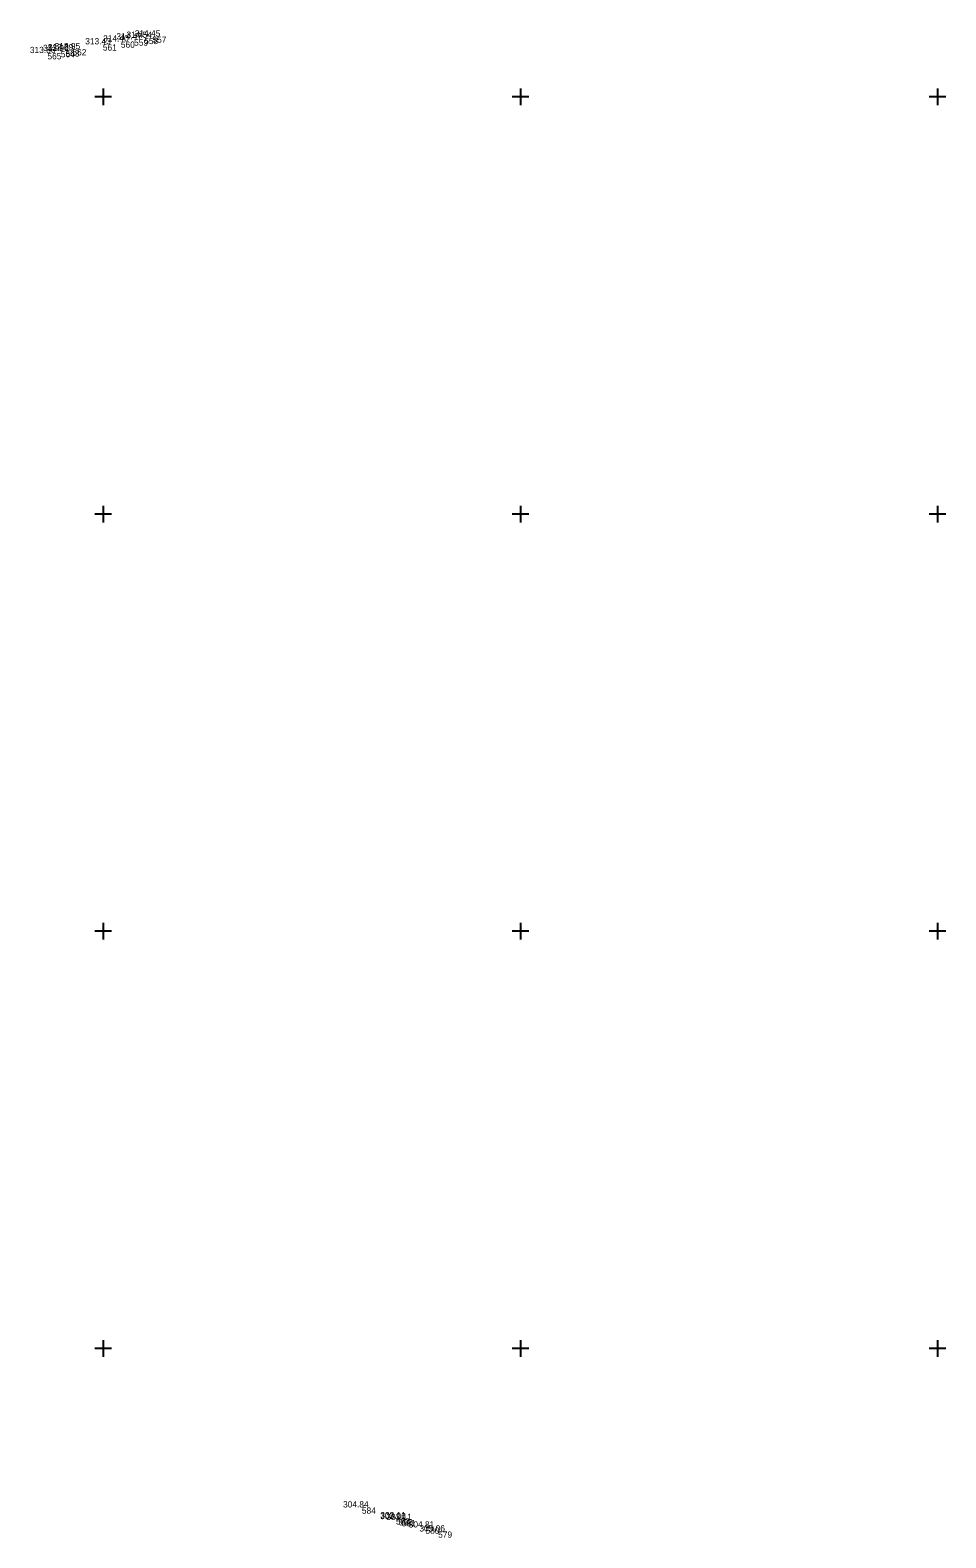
# Model space of a CAD drawing. Extents: x -718951 to -718443, y -1070201 to -1068444.
# Drawn here: x -718858.8 to -718749, y -1069972.7 to -1069792 of the extents above; entities that cross this region are included whole.
import ezdxf

# ---------------------------------------------------------------- set-up
doc = ezdxf.new("R2010")
doc.units = 0
for name, color, linetype in [('GEO_Body polohopis', 7, 'Continuous'), ('GEO_Hektarová síť', 7, 'Continuous'), ('GEO_Výšky bodů polohopis', 7, 'Continuous'), ('GEO_Čísla bodů polohopis', 7, 'Continuous')]:
    doc.layers.add(name, color=color, linetype=linetype)

msp = doc.modelspace()

# ---------------------------------------------------------------- linework, layer by layer
at = {"layer": 'GEO_Body polohopis'}
for p, q in [((-718855.09, -1069794.5), (-718855.09, -1069794.5)), ((-718854.52, -1069794.41), (-718854.52, -1069794.41)), ((-718853.7, -1069794.28), (-718853.7, -1069794.28)), ((-718850.05, -1069793.7), (-718850.05, -1069793.7)), ((-718847.89, -1069793.36), (-718847.89, -1069793.36)), ((-718846.3, -1069793.11), (-718846.3, -1069793.11)), ((-718845.09, -1069792.92), (-718845.09, -1069792.92)), ((-718844.1, -1069792.76), (-718844.1, -1069792.76)), ((-718856.69, -1069794.75), (-718856.69, -1069794.75)), ((-718819, -1069969.06), (-718819, -1069969.06)), ((-718814.92, -1069970.35), (-718814.92, -1069970.35)), ((-718814.57, -1069970.46), (-718814.57, -1069970.46)), ((-718814.21, -1069970.57), (-718814.21, -1069970.57)), ((-718811.38, -1069971.46), (-718811.38, -1069971.46)), ((-718809.86, -1069971.94), (-718809.86, -1069971.94))]:
    msp.add_line(p, q, dxfattribs=at)
at = {"layer": 'GEO_Hektarová síť'}
for points in [[(-718850, -1069799), (-718850, -1069800), (-718850, -1069801)], [(-718800, -1069799), (-718800, -1069800), (-718800, -1069801)], [(-718750, -1069799), (-718750, -1069800), (-718750, -1069801)], [(-718849, -1069800), (-718850, -1069800), (-718851, -1069800)], [(-718799, -1069800), (-718800, -1069800), (-718801, -1069800)], [(-718749, -1069800), (-718750, -1069800), (-718751, -1069800)], [(-718849, -1069850), (-718850, -1069850), (-718851, -1069850)], [(-718850, -1069849), (-718850, -1069850), (-718850, -1069851)], [(-718799, -1069850), (-718800, -1069850), (-718801, -1069850)], [(-718800, -1069849), (-718800, -1069850), (-718800, -1069851)], [(-718749, -1069850), (-718750, -1069850), (-718751, -1069850)], [(-718750, -1069849), (-718750, -1069850), (-718750, -1069851)], [(-718850, -1069899), (-718850, -1069900), (-718850, -1069901)], [(-718800, -1069899), (-718800, -1069900), (-718800, -1069901)], [(-718750, -1069899), (-718750, -1069900), (-718750, -1069901)], [(-718849, -1069900), (-718850, -1069900), (-718851, -1069900)], [(-718799, -1069900), (-718800, -1069900), (-718801, -1069900)], [(-718749, -1069900), (-718750, -1069900), (-718751, -1069900)], [(-718850, -1069949), (-718850, -1069950), (-718850, -1069951)], [(-718800, -1069949), (-718800, -1069950), (-718800, -1069951)], [(-718750, -1069949), (-718750, -1069950), (-718750, -1069951)], [(-718849, -1069950), (-718850, -1069950), (-718851, -1069950)], [(-718799, -1069950), (-718800, -1069950), (-718801, -1069950)], [(-718749, -1069950), (-718750, -1069950), (-718751, -1069950)]]:
    msp.add_lwpolyline(points, dxfattribs=at)

# ---------------------------------------------------------------- texts
at = {"layer": 'GEO_Výšky bodů polohopis'}
for s, p in [('314.40 ', (-718850.02, -1069793.36)), ('314.47 ', (-718848.43, -1069793.11)), ('314.54 ', (-718847.22, -1069792.92)), ('314.45 ', (-718846.23, -1069792.76)), ('313.86 ', (-718858.8, -1069794.75)), ('312.90 ', (-718857.22, -1069794.5)), ('312.89 ', (-718856.65, -1069794.41)), ('312.95 ', (-718855.83, -1069794.28)), ('313.43 ', (-718852.16, -1069793.7)), ('304.84 ', (-718821.26, -1069969.06)), ('303.06 ', (-718816.81, -1069970.46)), ('303.11 ', (-718816.79, -1069970.35)), ('303.11 ', (-718816.08, -1069970.57)), ('304.81 ', (-718813.39, -1069971.46)), ('305.06 ', (-718812.11, -1069971.94))]:
    msp.add_text(s, height=0.75, dxfattribs=at).set_placement(p)
at = {"layer": 'GEO_Čísla bodů polohopis'}
for s, p in [('564', (-718855.09, -1069795.25)), ('563', (-718854.52, -1069795.16)), ('562', (-718853.7, -1069795.03)), ('561', (-718850.05, -1069794.45)), ('560', (-718847.89, -1069794.11)), ('559', (-718846.3, -1069793.86)), ('558', (-718845.09, -1069793.67)), ('557', (-718844.1, -1069793.51)), ('565', (-718856.69, -1069795.5)), ('584', (-718819, -1069969.81)), ('583', (-718814.92, -1069971.1)), ('582', (-718814.57, -1069971.21)), ('581', (-718814.21, -1069971.32)), ('580', (-718811.38, -1069972.21)), ('579', (-718809.86, -1069972.69))]:
    msp.add_text(s, height=0.75, dxfattribs=at).set_placement(p)

doc.saveas('drawing.dxf')
